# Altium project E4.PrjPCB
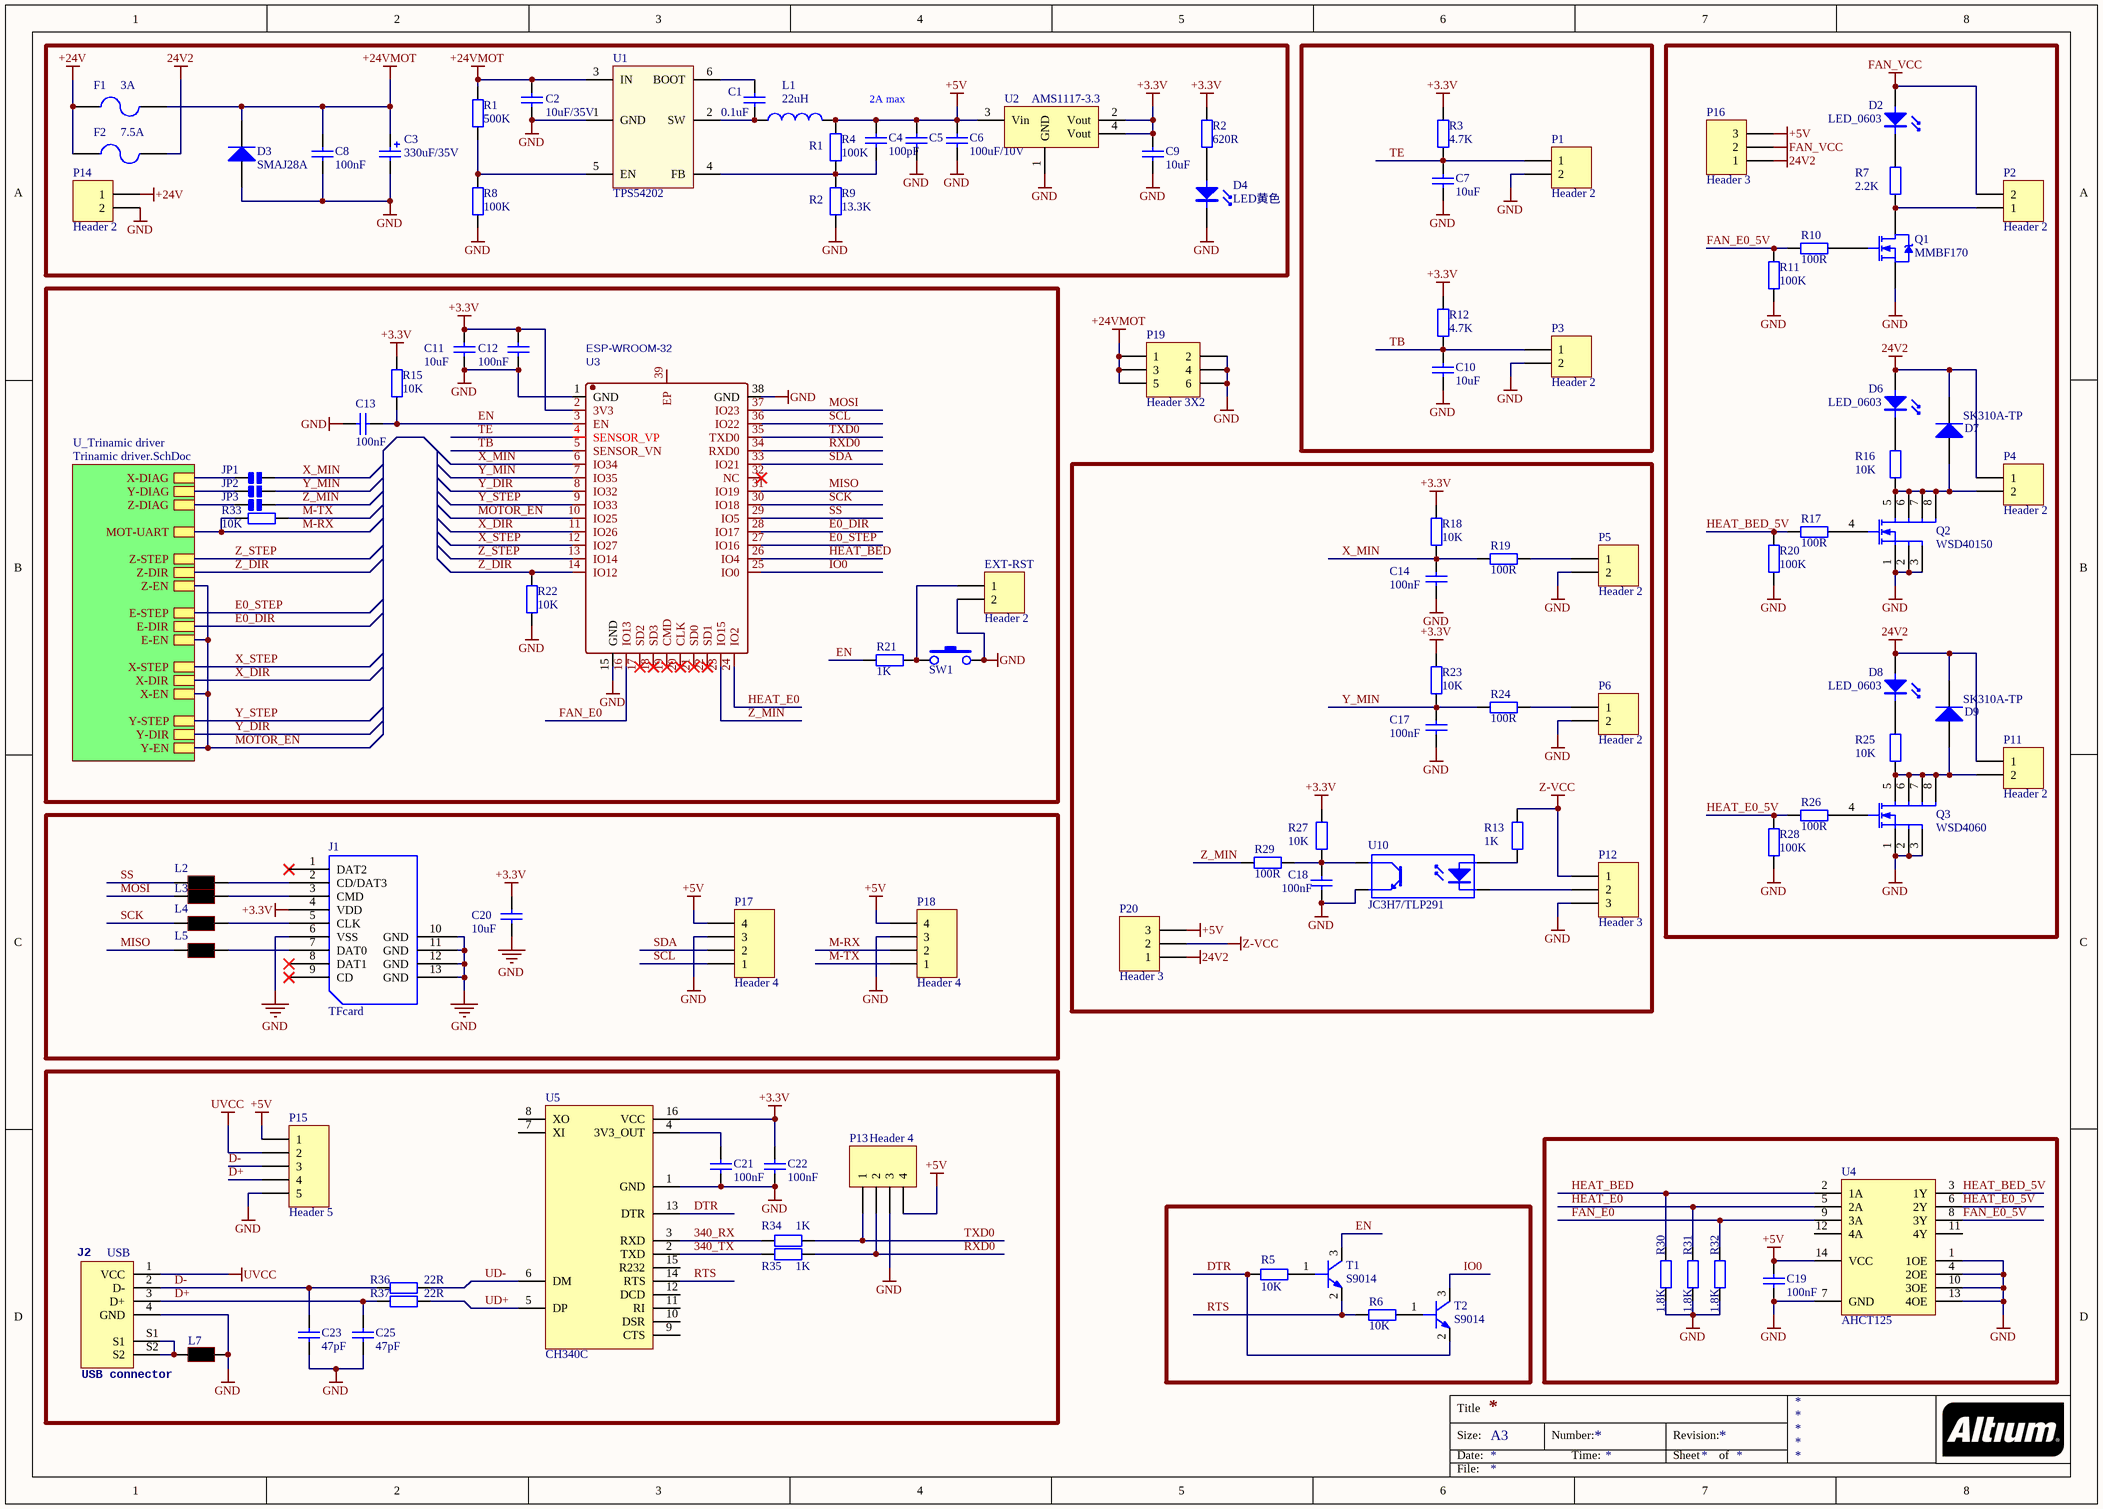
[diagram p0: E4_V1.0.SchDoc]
2 sheets, 151 parts. Net scope: hierarchical (ports join the sheet entries above them; power ports are global).
Board file: E4 V1.0B.PcbDoc
Sheets:
  E4_V1.0.SchDoc
    U_Trinamic driver = Trinamic driver.SchDoc

## Sheet E4_V1.0.SchDoc
size A3

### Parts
C1  0.1uF  [CAP0402]
C2  10uF/35V  [CAP1206]
C3  330uF/35V  [CASE_E7]
C4  100pF  [CAP0402]
C5  100uF/10V  [CAP1206]  (value not drawn)
C6  100uF/10V  [CAP1206]
C7  10uF  [CAP0805]
C8  100nF  [CAP0603]
C9  10uF  [CAP0805]
C10  10uF  [CAP0805]
C11  10uF  [CAP0805]
C12  100nF  [CAP0402]
C13  100nF  [CAP0402]
C14  100nF  [CAP0402]
C17  100nF  [CAP0402]
C18  100nF  [CAP0402]
C19  100nF  [CAP0402]
C20  10uF  [CAP0603]
C21  100nF  [CAP0402]
C22  100nF  [CAP0402]
C23  47pF  [CAP0402]
C25  47pF  [CAP0402]
D2  LED_0603  [LED0603]
D3  SMAJ28A  [DO214AC (SMA)]
D4  LED黄色  [LED0603]
D6  LED_0603  [LED0603]
D7  SK310A-TP  [DO214AC (SMA)]
D8  LED_0603  [LED0603]
D9  SK310A-TP  [DO214AC (SMA)]
EXT-RST  Header 2  [HDR1X2]
F1  3A  [MCCQ-122]
F2  7.5A  [MCCQ-122]
J1  TFcard  [MicroSD_1]
J2  USB connector  [CON-BERG_PN61729-S]
JP1  Jumper-2P-Open  [HDR1X2]  (value not drawn)
JP2  Jumper-2P-Open  [HDR1X2]  (value not drawn)
JP3  Jumper-2P-Open  [HDR1X2]  (value not drawn)
L1  22uH  [NRS6045]
L2  Bead  [RES0603]  (value not drawn)
L3  Bead  [RES0603]  (value not drawn)
L4  Bead  [RES0603]  (value not drawn)
L5  Bead  [RES0603]  (value not drawn)
L7  Bead  [L0805]  (value not drawn)
P1  Header 2  [XH2.54-2P-L]
P2  Header 2  [XH2.54-2P-L]
P3  Header 2  [XH2.54-2P-L]
P4  Header 2  [KF128/129]
P5  Header 2  [XH2.54-2P-L]
P6  Header 2  [XH2.54-2P-L]
P11  Header 2  [KF128/129]
P12  Header 3  [XH2.54-3P-L]
P13  Header 4  [Header 1X4]
P14  Header 2  [KF128/129]
P15  Header 5  [Header 1X5]
P16  Header 3  [HDR1X3]
P17  Header 4  [Header 1X4]
P18  Header 4  [Header 1X4]
P19  Header 3X2  [Header 2X3]
P20  Header 3  [HDR1X3]
Q1  MMBF170  [SOT23-3]
Q2  WSD40150  [AO_DFN5x6]
Q3  WSD4060  [AO_DFN5x6]
R1  500K  [RES0402]
R2  620R  [RES0402]
R3  4.7K  [RES0603]
R4  100K  [RES0402]
R5  10K  [RES0402]
R6  10K  [RES0402]
R7  2.2K  [RES0402]
R8  100K  [RES0402]
R9  13.3K  [RES0402]
R10  100R  [RES0402]
R11  100K  [RES0402]
R12  4.7K  [RES0603]
R13  1K  [RES0402]
R15  10K  [RES0402]
R16  10K  [RES0402]
R17  100R  [RES0402]
R18  10K  [RES0402]
R19  100R  [RES0402]
R20  100K  [RES0402]
R21  1K  [RES0402]
R22  10K  [RES0402]
R23  10K  [RES0402]
R24  100R  [RES0402]
R25  10K  [RES0402]
R26  100R  [RES0402]
R27  10K  [RES0402]
R28  100K  [RES0402]
R29  100R  [RES0402]
R30  1.8K  [RES0402]
R31  1.8K  [RES0402]
R32  1.8K  [RES0402]
R33  10K  [RES0402]
R34  1K  [RES0402]
R35  1K  [RES0402]
R36  22R  [RES0402]
R37  22R  [RES0402]
SW1  Momentary Tactile Button  [7.5x6x6.5 侧按开关]  (value not drawn)
T1  S9014  [SOT323_3_SC70]
T2  S9014  [SOT323_3_SC70]
U1  TPS54202  [SOT23-6N]
U2  AMS1117-3.3  [SOT-223]
U3  ESP-WROOM-32  [WIFIM-SMD_ESP-WROOM-32]
U4  AHCT125  [QFN14]
U5  CH340C  [SOP16]
U10  JC3H7/TLP291  [SOIC127P720X210-4N]

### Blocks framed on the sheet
USB: C21-C23 C25 J2 L7 P13 P15 R34-R37 U5

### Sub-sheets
U_Trinamic driver = Trinamic driver.SchDoc: Z-STEP, Z-DIR, Z-EN, Z-DIAG, MOT-UART, X-STEP, X-DIR, X-EN, X-DIAG, E-STEP, E-DIR, E-EN, Y-STEP, Y-DIR, Y-EN, Y-DIAG

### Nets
24V2: D6.2(K) D7.2(K) D8.2(K) D9.2(K) F2.2 P4.1 P11.1 P16.1 P20.1
+3.3V: C9.2 C11.1 C12.2 C20.1 C22.2 J1.4(VDD) R2.1 R3.2 R12.2 R15.2 R18.1 R23.1 R27.1 U2.2(Vout) U2.4(Vout) U3.2(3V3) U5.16(VCC)
+5V: C4.1 C5.1 C6.1 C19.2 L1.2 P13.4 P15.1 P16.3 P17.4 P18.4 P20.3 R4.1 U2.3(Vin) U4.14(VCC)
+24V: F1.1 F2.1 P14.1
+24VMOT: C2.2 C3.1 C8.2 D3.2(K) F1.2 P19.1 P19.3 P19.5 R1.2 U1.3(IN)
FAN_VCC: D2.2(K) P2.2 P16.2
GND: C2.1 C3.2 C5.2 C6.2 C7.1 C8.1 C9.1 C10.1 C11.2 C12.1 C13.2 C14.2 C17.2 C18.2 C19.1 C20.2 C21.1 C22.1 C23.1 C25.1 D3.1(A) D4.1(A) EXT-RST.2 J1.6(VSS) J1.10(GND) J1.11(GND) J1.12(GND) J1.13(GND) J2.4(GND) L7.2 P1.2 P3.2 P5.2 P6.2 P12.3 P13.3 P14.2 P15.5 P17.3 P18.3 P19.2 P19.4 P19.6 Q1.2(S) Q2.1(S) Q2.2(S) Q2.3(S) Q3.1(S) Q3.2(S) Q3.3(S) R8.1 R9.2 R11.2 R20.2 R22.1 R28.2 R30.2 R31.2 R32.2 SW1.2 U1.1(GND) U2.1(GND) U3.1(GND) U3.15(GND) U3.38(GND) U4.1(1OE) U4.4(2OE) U4.7(GND) U4.10(3OE) U4.13(4OE) U5.1(GND) U10.3(E)
UVCC: J2.1(VCC) P15.2
Z-VCC: P12.1 P20.2 R13.2
340_RX: R34.1 U5.3(RXD)
340_TX: R35.1 U5.2(TXD)
D+: C25.2 J2.3(D+) P15.4 R37.1
D-: C23.2 J2.2(D-) P15.3 R36.1
DTR: R5.1 T2.2(EMITTER) U5.13(DTR)
E0_DIR: U3.28(IO17) ; sheet U_Trinamic driver/E-DIR
E0_STEP: U3.27(IO16) ; sheet U_Trinamic driver/E-STEP
EN: C13.1 R15.1 R21.2 T1.3(COLLECTOR) U3.3(EN)
FAN_E0: R32.1 U3.16(IO13) U4.9(3A)
FAN_E0_5V: R10.2 R11.1 U4.8(3Y)
HEAT_BED: R30.1 U3.26(IO4) U4.2(1A)
HEAT_BED_5V: R17.2 R20.1 U4.3(1Y)
HEAT_E0: R31.1 U3.24(IO2) U4.5(2A)
HEAT_E0_5V: R26.2 R28.1 U4.6(2Y)
IO0: T2.3(COLLECTOR) U3.25(IO0)
M-RX: P18.2 R33.2 ; sheet U_Trinamic driver/MOT-UART
M-TX: P18.1 R33.1
MISO: L5.1 U3.31(IO19)
MOSI: L3.1 U3.37(IO23)
MOTOR_EN: U3.10(IO25) ; sheet U_Trinamic driver/Z-EN, sheet U_Trinamic driver/X-EN, sheet U_Trinamic driver/E-EN, sheet U_Trinamic driver/Y-EN
RTS: R6.2 T1.2(EMITTER) U5.14(RTS)
RXD0: P13.2 R35.2 U3.34(RXD0)
SCK: L4.1 U3.30(IO18)
SCL: P17.1 U3.36(IO22)
SDA: P17.2 U3.33(IO21)
SS: L2.1 U3.29(IO5)
TB: C10.2 P3.1 R12.1 U3.5(SENSOR_VN)
TE: C7.2 P1.1 R3.1 U3.4(SENSOR_VP)
TXD0: P13.1 R34.2 U3.35(TXD0)
UD+: R37.2 U5.5(DP)
UD-: R36.2 U5.6(DM)
X-DIAG: JP1.1 ; sheet U_Trinamic driver/X-DIAG
X_DIR: U3.11(IO26) ; sheet U_Trinamic driver/X-DIR
X_MIN: C14.1 JP1.2 R18.2 R19.2 U3.6(IO34)
X_STEP: U3.12(IO27) ; sheet U_Trinamic driver/X-STEP
Y-DIAG: JP2.1 ; sheet U_Trinamic driver/Y-DIAG
Y_DIR: U3.8(IO32) ; sheet U_Trinamic driver/Y-DIR
Y_MIN: C17.1 JP2.2 R23.2 R24.2 U3.7(IO35)
Y_STEP: U3.9(IO33) ; sheet U_Trinamic driver/Y-STEP
Z-DIAG: JP3.1 ; sheet U_Trinamic driver/Z-DIAG
Z_DIR: R22.2 U3.14(IO12) ; sheet U_Trinamic driver/Z-DIR
Z_MIN: JP3.2 R29.2 U3.23(IO15)
Z_STEP: U3.13(IO14) ; sheet U_Trinamic driver/Z-STEP
NetC1_1: C1.1 U1.6(BOOT)
NetC1_2: C1.2 L1.1 U1.2(SW)
NetC4_2: C4.2 R4.2 R9.1 U1.4(FB)
NetC18_1: C18.1 R27.2 R29.1 U10.4(C)
NetC21_2: C21.2 U5.4(3V3_OUT)
NetD2_1: D2.1(A) R7.2
NetD4_2: D4.2(K) R2.2
NetD6_1: D6.1(A) R16.2
NetD7_1: D7.1(A) P4.2 Q2.5(D) Q2.6(D) Q2.7(D) Q2.8(D) R16.1
NetD8_1: D8.1(A) R25.2
NetD9_1: D9.1(A) P11.2 Q3.5(D) Q3.6(D) Q3.7(D) Q3.8(D) R25.1
NetEXT-RST_1: EXT-RST.1 R21.1 SW1.1
NetJ1_2: J1.2(CD/DAT3) L2.2
NetJ1_3: J1.3(CMD) L3.2
NetJ1_5: J1.5(CLK) L4.2
NetJ1_7: J1.7(DAT0) L5.2
NetJ2_S1: J2.S1 J2.S2 L7.1
NetP2_1: P2.1 Q1.3(D) R7.1
NetP5_1: P5.1 R19.1
NetP6_1: P6.1 R24.1
NetP12_2: P12.2 U10.2(K)
NetQ1_1: Q1.1(G) R10.1
NetQ2_4: Q2.4(G) R17.1
NetQ3_4: Q3.4(G) R26.1
NetR1_1: R1.1 R8.2 U1.5(EN)
NetR5_2: R5.2 T1.1(BASE)
NetR6_1: R6.1 T2.1(BASE)
NetR13_1: R13.1 U10.1(A)

Not connected (* = marked no-connect by the designer): J1 1(DAT2)* 8(DAT1)* 9(CD)*; U3 17(SD2)* 18(SD3)* 19(CMD)* 20(CLK)* 21(SD0)* 22(SD1)* 32(NC)* 39(EP); U4 11(4Y) 12(4A); U5 7(XI) 8(XO) 9(CTS) 10(DSR) 11(RI) 12(DCD) 15(R232)

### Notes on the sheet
- 2A max
- R1
- (near R9) R2

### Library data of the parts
C1 = Library_CAP-0008: RO C0G 22pF 2% 50V  0603; Faber ItemCode: 35321100; Value: 100nF
C2 C7-C13 C20 = Capacitor
C3 = Library_CAP-0004: RO ELCO 100uF 20% 35V CASE-D EEEFP PAN; Faber ItemCode: 36865800
C4 = Library_CAP-0008: RO C0G 22pF 2% 50V  0603; Faber ItemCode: 35321100; Value: 47pF
C5 C6 = Library_CAP-0008: RO C0G 22pF 2% 50V  0603; Faber ItemCode: 35321100; Value: 47uF
C14 C17-C19 = Library_CAP-0008: RO C0G 22pF 2% 50V  0603; Faber ItemCode: 35321100
C21 C22 = Library_CAP-0006: RO X5R 1uF 10% 10V 0603; Faber ItemCode: 36310600
C23 C25 = Library_CAP-0002: RO X7R 100nF 10% 50V 0603; Faber ItemCode: 45068500
D3 D7 D9 = Diode: Default Diode
D4 = LED_0603
EXT-RST P1-P6 P11 P14 = Header 2: Header, 2-Pin
F1 F2 = Fuse 2: Fuse
J2 = CON-BERG_PN61729-S
L1 = Inductor: Code_IEC: 1005
L2-L5 = Bead: RO FERRIET BLM21PG221SN1D  0805; ID: Library_COIL-0001; Faber ItemCode: 36571200
L7 = Library_COIL-0001: RO FERRIET BLM21PG221SN1D  0805; Faber ItemCode: 36571200
P12 P16 P20 = Header 3: Header, 3-Pin
P13 P17 P18 = Header 4: Header, 4-Pin
P15 = Header 5: Header, 5-Pin
P19 = Header 3X2: Header, 3-Pin, Dual row
Q1 = N-MOS
Q2 Q3 = MOSFET-N-SO8: IRF8736PBF - MOSFET, N SO-8; Mfg: INTERNATIONAL RECTIFIER; ID: LIBRARY_FET-0002; Info: HEXFET Power MOSFET; Faber ItemCode: 36926000
R1 R3 R7 R8 R10-R13 R15-R33 = Resistor
R2 R4 = Library_RES-0001: RO RES 10k0 1% 0,063W  0603; Faber ItemCode: 36084500; Value: 49.9k
R5 R6 R34-R37 = Library_RES-0007: RO RES 22E0 1% 0,063W 0603; Faber ItemCode: 36108300
R9 = Library_RES-0001: RO RES 10k0 1% 0,063W  0603; Faber ItemCode: 36084500; Value: 9.53k
SW1 = SW-PB: SWITCH TACTILE SPST-NO 0.05A 12V; Note: Approved sub OK
T1 T2 = Transistor NPN: RO TRANS BC817-25  SOT-23; ID: Library_TRA-0001; Faber ItemCode: 30828000; Info: 45 V, 500 mA NPN general-purpose transistors
U2 = 1117
U3 = ESP-WROOM-32: BOM_Manufacturer: ESPRESSIF
U4 = 74HC125
U5 = CH340G
U10 = Optoisolator1: 4-Pin Phototransistor Optocoupler

## Sheet Trinamic driver.SchDoc
size A4
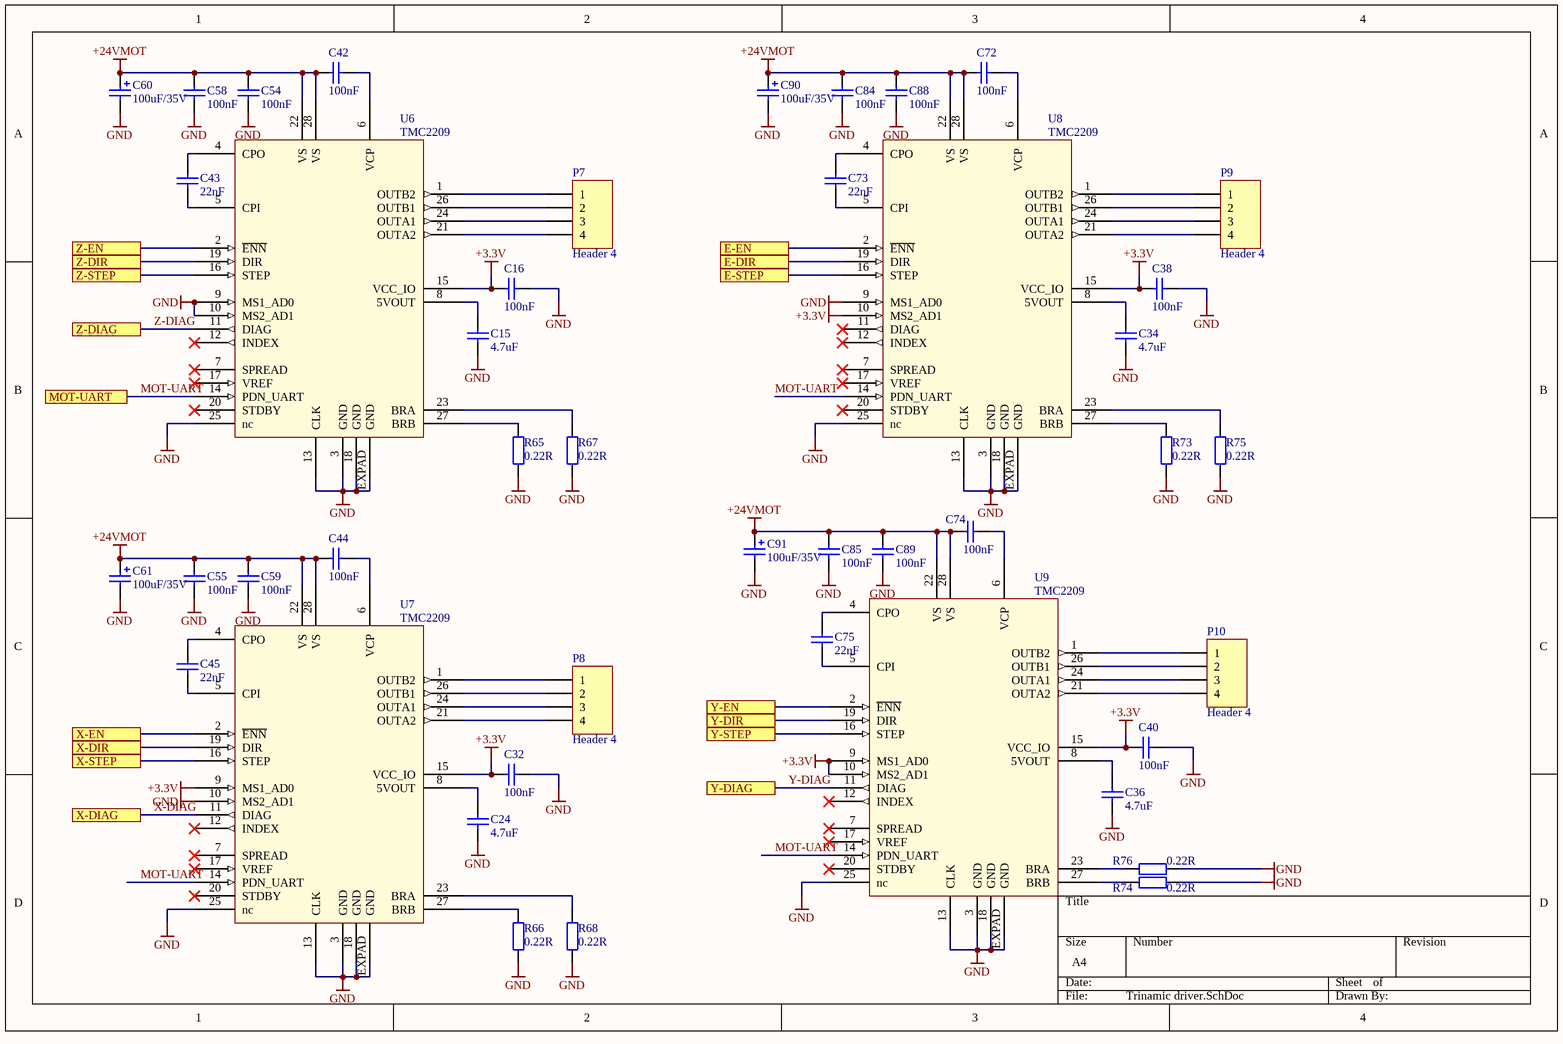
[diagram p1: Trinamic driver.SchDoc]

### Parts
C15  4.7uF  [CAP0603]
C16  100nF  [CAP0402]
C24  4.7uF  [CAP0603]
C32  100nF  [CAP0402]
C34  4.7uF  [CAP0603]
C36  4.7uF  [CAP0603]
C38  100nF  [CAP0402]
C40  100nF  [CAP0402]
C42  100nF  [CAP0402]
C43  22nF  [CAP0402]
C44  100nF  [CAP0402]
C45  22nF  [CAP0402]
C54  100nF  [CAP0603]
C55  100nF  [CAP0603]
C58  100nF  [CAP0603]
C59  100nF  [CAP0603]
C60  100uF/35V  [ELCO Case D]
C61  100uF/35V  [ELCO Case D]
C72  100nF  [CAP0402]
C73  22nF  [CAP0402]
C74  100nF  [CAP0402]
C75  22nF  [CAP0402]
C84  100nF  [CAP0603]
C85  100nF  [CAP0603]
C88  100nF  [CAP0603]
C89  100nF  [CAP0603]
C90  100uF/35V  [ELCO Case D]
C91  100uF/35V  [ELCO Case D]
P7  Header 4  [XH2.54-4P-L]
P8  Header 4  [XH2.54-4P-L]
P9  Header 4  [XH2.54-4P-L]
P10  Header 4  [XH2.54-4P-L]
R65  0.22R  [RES0805]
R66  0.22R  [RES0805]
R67  0.22R  [RES0805]
R68  0.22R  [RES0805]
R73  0.22R  [RES0805]
R74  0.22R  [RES0805]
R75  0.22R  [RES0805]
R76  0.22R  [RES0805]
U6  TMC2209  [QFN28 (2209)]
U7  TMC2209  [QFN28 (2209)]
U8  TMC2209  [QFN28 (2209)]
U9  TMC2209  [QFN28 (2209)]

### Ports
E-DIR, E-EN, E-STEP, MOT-UART, X-DIAG, X-DIR, X-EN, X-STEP, Y-DIAG, Y-DIR, Y-EN, Y-STEP, Z-DIAG, Z-DIR, Z-EN, Z-STEP

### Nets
+3.3V: C16.2 C32.2 C38.2 C40.2 U6.15(VCC_IO) U7.9(MS1_AD0) U7.15(VCC_IO) U8.10(MS2_AD1) U8.15(VCC_IO) U9.9(MS1_AD0) U9.10(MS2_AD1) U9.15(VCC_IO)
+24VMOT: C42.1 C44.1 C54.2 C55.2 C58.2 C59.2 C60.1 C61.1 C72.1 C74.1 C84.2 C85.2 C88.2 C89.2 C90.1 C91.1 U6.22(VS) U6.28(VS) U7.22(VS) U7.28(VS) U8.22(VS) U8.28(VS) U9.22(VS) U9.28(VS)
GND: C15.2 C16.1 C24.2 C32.1 C34.2 C36.2 C38.1 C40.1 C54.1 C55.1 C58.1 C59.1 C60.2 C61.2 C84.1 C85.1 C88.1 C89.1 C90.2 C91.2 R65.1 R66.1 R67.1 R68.1 R73.1 R74.1 R75.1 R76.1 U6.3(GND) U6.9(MS1_AD0) U6.10(MS2_AD1) U6.13(CLK) U6.18(GND) U6.25(nc) U6.EXPAD(GND) U7.3(GND) U7.10(MS2_AD1) U7.13(CLK) U7.18(GND) U7.25(nc) U7.EXPAD(GND) U8.3(GND) U8.9(MS1_AD0) U8.13(CLK) U8.18(GND) U8.25(nc) U8.EXPAD(GND) U9.3(GND) U9.13(CLK) U9.18(GND) U9.25(nc) U9.EXPAD(GND)
E0_DIR: U8.19(DIR) ; port E-DIR
E0_STEP: U8.16(STEP) ; port E-STEP
MOT-UART: U6.14(PDN_UART) U7.14(PDN_UART) U8.14(PDN_UART) U9.14(PDN_UART) ; port MOT-UART  [project net M-RX]
MOTOR_EN: U6.2(~{ENN}) U7.2(~{ENN}) U8.2(~{ENN}) U9.2(~{ENN}) ; port Z-EN, port X-EN, port E-EN, port Y-EN
X-DIAG: U7.11(DIAG) ; port X-DIAG
X_DIR: U7.19(DIR) ; port X-DIR
X_STEP: U7.16(STEP) ; port X-STEP
Y-DIAG: U9.11(DIAG) ; port Y-DIAG
Y_DIR: U9.19(DIR) ; port Y-DIR
Y_STEP: U9.16(STEP) ; port Y-STEP
Z-DIAG: U6.11(DIAG) ; port Z-DIAG
Z_DIR: U6.19(DIR) ; port Z-DIR
Z_STEP: U6.16(STEP) ; port Z-STEP
NetC15_1: C15.1 U6.8(5VOUT)
NetC24_1: C24.1 U7.8(5VOUT)
NetC34_1: C34.1 U8.8(5VOUT)
NetC36_1: C36.1 U9.8(5VOUT)
NetC42_2: C42.2 U6.6(VCP)
NetC43_1: C43.1 U6.5(CPI)
NetC43_2: C43.2 U6.4(CPO)
NetC44_2: C44.2 U7.6(VCP)
NetC45_1: C45.1 U7.5(CPI)
NetC45_2: C45.2 U7.4(CPO)
NetC72_2: C72.2 U8.6(VCP)
NetC73_1: C73.1 U8.5(CPI)
NetC73_2: C73.2 U8.4(CPO)
NetC74_2: C74.2 U9.6(VCP)
NetC75_1: C75.1 U9.5(CPI)
NetC75_2: C75.2 U9.4(CPO)
NetP7_1: P7.1 U6.1(OUTB2)
NetP7_2: P7.2 U6.26(OUTB1)
NetP7_3: P7.3 U6.24(OUTA1)
NetP7_4: P7.4 U6.21(OUTA2)
NetP8_1: P8.1 U7.1(OUTB2)
NetP8_2: P8.2 U7.26(OUTB1)
NetP8_3: P8.3 U7.24(OUTA1)
NetP8_4: P8.4 U7.21(OUTA2)
NetP9_1: P9.1 U8.1(OUTB2)
NetP9_2: P9.2 U8.26(OUTB1)
NetP9_3: P9.3 U8.24(OUTA1)
NetP9_4: P9.4 U8.21(OUTA2)
NetP10_1: P10.1 U9.1(OUTB2)
NetP10_2: P10.2 U9.26(OUTB1)
NetP10_3: P10.3 U9.24(OUTA1)
NetP10_4: P10.4 U9.21(OUTA2)
NetR65_2: R65.2 U6.27(BRB)
NetR66_2: R66.2 U7.27(BRB)
NetR67_2: R67.2 U6.23(BRA)
NetR68_2: R68.2 U7.23(BRA)
NetR73_2: R73.2 U8.27(BRB)
NetR74_2: R74.2 U9.27(BRB)
NetR75_2: R75.2 U8.23(BRA)
NetR76_2: R76.2 U9.23(BRA)

Not connected (* = marked no-connect by the designer): U6 7(SPREAD)* 12(INDEX)* 17(VREF)* 20(STDBY)*; U7 7(SPREAD)* 12(INDEX)* 17(VREF)* 20(STDBY)*; U8 7(SPREAD)* 11(DIAG)* 12(INDEX)* 17(VREF)* 20(STDBY)*; U9 7(SPREAD)* 12(INDEX)* 17(VREF)* 20(STDBY)*

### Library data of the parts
C15 C24 C34 C36 C43 C45 C73 C75 = Library_CAP-0008: as C1 on sheet E4_V1.0
C16 C32 C38 C40 = Library_CAP-0008: as C14 on sheet E4_V1.0
C42 C44 C54 C55 C58 C59 C72 C74 C84 C85 C88 C89 = Capacitor
C60 C61 C90 C91 = Capacitor Polarity: RO ELCO 100uF 20% 35V CASE-D EEEFP PAN; ID: Library_CAP-0004; Faber ItemCode: 36865800
P7-P10 = Header 4: Header, 4-Pin
R65-R68 R73-R76 = Resistor

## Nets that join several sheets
+3.3V: E4_V1.0 (17 pins), Trinamic driver (12 pins)
+24VMOT: E4_V1.0 (10 pins), Trinamic driver (24 pins)
GND: E4_V1.0 (72 pins), Trinamic driver (52 pins)
E0_DIR: E4_V1.0 (U3.28), Trinamic driver (U8.19)
E0_STEP: E4_V1.0 (U3.27), Trinamic driver (U8.16)
M-RX: E4_V1.0 (P18.2 R33.2), Trinamic driver (U6.14 U7.14 U8.14 U9.14)
MOTOR_EN: E4_V1.0 (U3.10), Trinamic driver (U6.2 U7.2 U8.2 U9.2)
X-DIAG: E4_V1.0 (JP1.1), Trinamic driver (U7.11)
X_DIR: E4_V1.0 (U3.11), Trinamic driver (U7.19)
X_STEP: E4_V1.0 (U3.12), Trinamic driver (U7.16)
Y-DIAG: E4_V1.0 (JP2.1), Trinamic driver (U9.11)
Y_DIR: E4_V1.0 (U3.8), Trinamic driver (U9.19)
Y_STEP: E4_V1.0 (U3.9), Trinamic driver (U9.16)
Z-DIAG: E4_V1.0 (JP3.1), Trinamic driver (U6.11)
Z_DIR: E4_V1.0 (R22.2 U3.14), Trinamic driver (U6.19)
Z_STEP: E4_V1.0 (U3.13), Trinamic driver (U6.16)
